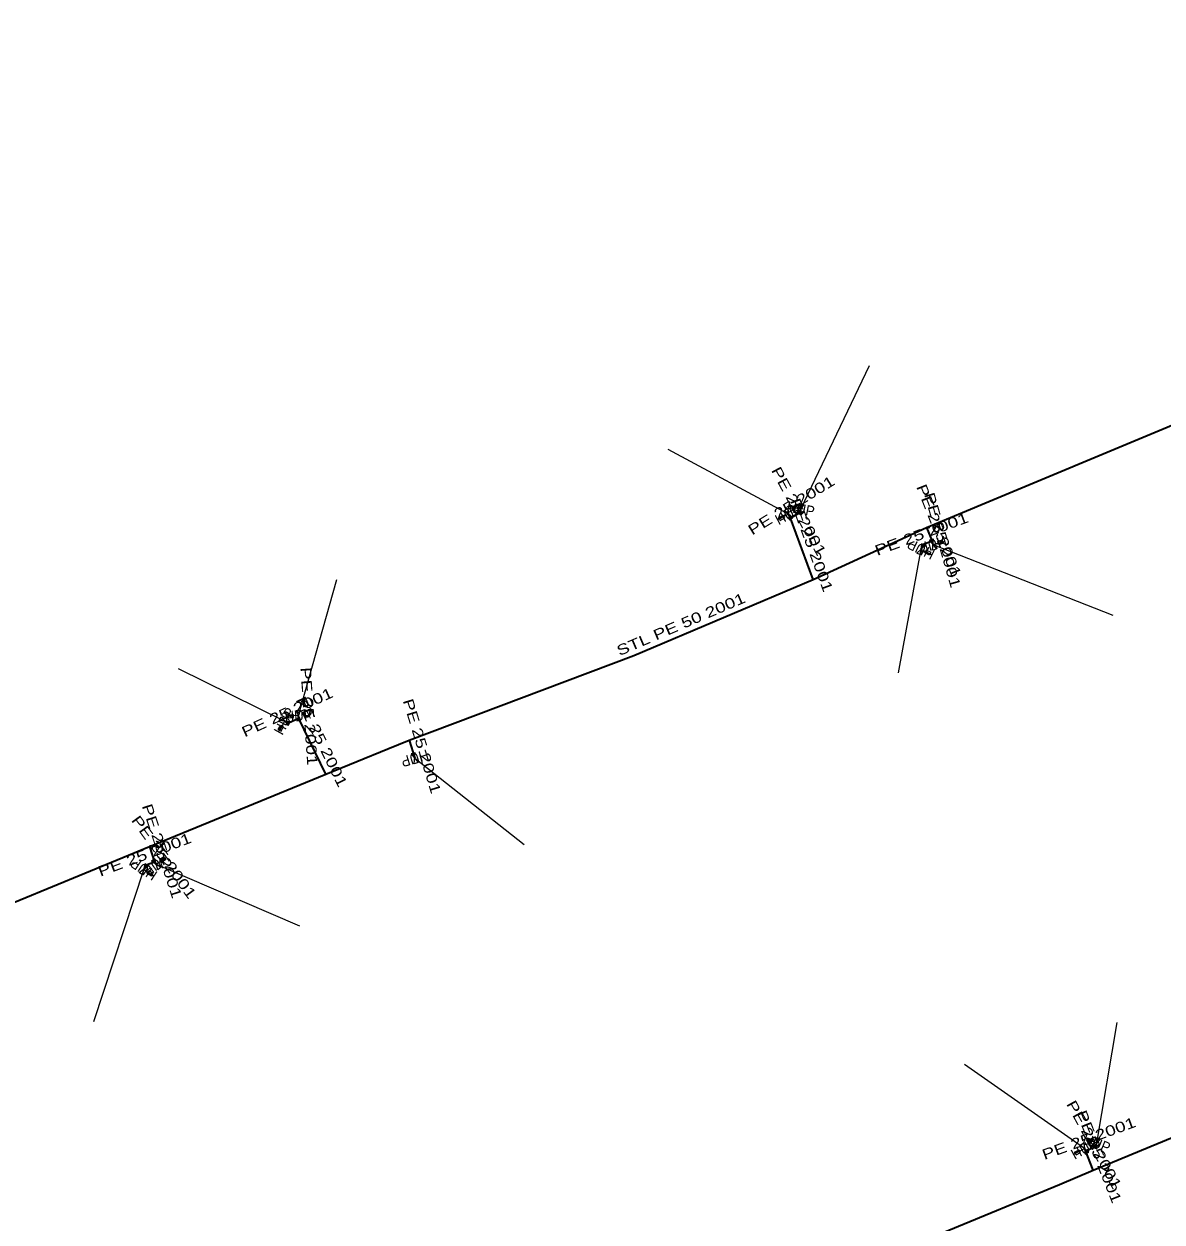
# Model space of a CAD drawing. Extents: x -737484 to -734496, y -1033882 to -1030666.
# Drawn here: x -735034.9 to -734925.7, y -1033417 to -1033302.1 of the extents above; entities that cross this region are included whole.
import ezdxf
from ezdxf.enums import TextEntityAlignment as Align

# ---------------------------------------------------------------- set-up
doc = ezdxf.new("R2010")
doc.units = 0
doc.header["$LTSCALE"] = 0.4
for name, color, linetype, lineweight in [('1', 7, 'Continuous', 13), ('22', 7, 'Continuous', 25), ('5', 7, 'Continuous', 35), ('7', 7, 'Continuous', 35)]:
    doc.layers.add(name, color=color, linetype=linetype, lineweight=lineweight)
doc.layers.add('2', color=7, linetype='Continuous')

msp = doc.modelspace()

# ---------------------------------------------------------------- linework, layer by layer
at = {"layer": '1'}
for p, q in [((-734962.092, -1033349.333), (-734962.401, -1033349.498)), ((-734961.55, -1033349.13), (-734961.991, -1033349.364)), ((-734960.93, -1033348.456), (-734961.273, -1033348.389)), ((-734960.38, -1033348.64), (-734960.87, -1033348.544)), ((-734948.85, -1033352.5), (-734948.4, -1033352.719)), ((-734948.366, -1033352.819), (-734948.051, -1033352.972)), ((-734947.7, -1033352.05), (-734947.219, -1033351.912)), ((-734947.126, -1033351.963), (-734946.79, -1033351.867)), ((-735009.89, -1033368.98), (-735010.124, -1033369.421)), ((-735009.128, -1033368.415), (-735009.477, -1033368.439)), ((-735008.55, -1033368.45), (-735009.048, -1033368.484)), ((-735010.226, -1033369.452), (-735010.39, -1033369.761)), ((-735022.19, -1033382.71), (-735021.785, -1033382.416)), ((-735021.68, -1033382.432), (-735021.397, -1033382.226)), ((-735023.4, -1033383.18), (-735022.98, -1033383.452)), ((-735022.958, -1033383.556), (-735022.665, -1033383.746)), ((-734932.499, -1033409.173), (-734932.826, -1033409.048)), ((-734933.709, -1033410.183), (-734934.015, -1033410.352)), ((-734933.17, -1033409.97), (-734933.607, -1033410.212)), ((-734931.99, -1033409.45), (-734932.456, -1033409.27))]:
    msp.add_line(p, q, dxfattribs=at)
for points in [[(-734961.361, -1033348.449), (-734961.333, -1033348.301), (-734960.842, -1033348.397), (-734960.87, -1033348.544)], [(-734961.317, -1033348.42), (-734961.302, -1033348.346), (-734960.885, -1033348.427), (-734960.9, -1033348.501)], [(-734960.48, -1033348.11), (-734960.088, -1033348.186), (-734960.671, -1033349.091), (-734960.279, -1033349.167)], [(-734962.432, -1033349.599), (-734962.503, -1033349.467), (-734962.061, -1033349.232), (-734961.991, -1033349.364)], [(-734962.416, -1033349.548), (-734962.451, -1033349.482), (-734962.076, -1033349.283), (-734962.041, -1033349.349)], [(-734962.432, -1033349.599), (-734962.362, -1033349.731), (-734961.921, -1033349.497), (-734961.991, -1033349.364)], [(-734961.961, -1033348.781), (-734961.608, -1033348.593), (-734961.491, -1033349.664), (-734961.138, -1033349.476)], [(-734961.361, -1033348.449), (-734961.39, -1033348.596), (-734960.899, -1033348.691), (-734960.87, -1033348.544)], [(-734947.368, -1033352.474), (-734947.753, -1033352.584), (-734947.644, -1033351.513), (-734948.029, -1033351.623)], [(-734946.738, -1033351.774), (-734946.78, -1033351.63), (-734947.26, -1033351.767), (-734947.219, -1033351.912)], [(-734946.738, -1033351.774), (-734946.697, -1033351.918), (-734947.178, -1033352.056), (-734947.219, -1033351.912)], [(-734948.888, -1033353.036), (-734949.247, -1033352.86), (-734948.45, -1033352.137), (-734948.809, -1033351.961)], [(-734947.951, -1033352.938), (-734948.016, -1033353.073), (-734948.466, -1033352.854), (-734948.4, -1033352.719)], [(-734948.001, -1033352.954), (-734948.034, -1033353.022), (-734948.416, -1033352.836), (-734948.383, -1033352.768)], [(-734947.951, -1033352.938), (-734947.885, -1033352.803), (-734948.334, -1033352.584), (-734948.4, -1033352.719)], [(-734946.765, -1033351.82), (-734946.744, -1033351.892), (-734947.152, -1033352.009), (-734947.173, -1033351.937)], [(-735010.423, -1033368.911), (-735010.229, -1033368.561), (-735009.548, -1033369.396), (-735009.354, -1033369.046)], [(-735009.547, -1033368.519), (-735009.558, -1033368.37), (-735009.059, -1033368.335), (-735009.048, -1033368.484)], [(-735009.547, -1033368.519), (-735009.537, -1033368.669), (-735009.038, -1033368.634), (-735009.048, -1033368.484)], [(-735009.512, -1033368.48), (-735009.517, -1033368.405), (-735009.093, -1033368.375), (-735009.088, -1033368.45)], [(-735008.784, -1033367.964), (-735008.385, -1033367.936), (-735008.714, -1033368.961), (-735008.315, -1033368.933)], [(-735010.359, -1033369.862), (-735010.491, -1033369.792), (-735010.257, -1033369.351), (-735010.124, -1033369.421)], [(-735010.374, -1033369.812), (-735010.44, -1033369.776), (-735010.24, -1033369.401), (-735010.174, -1033369.436)], [(-735010.359, -1033369.862), (-735010.227, -1033369.933), (-735009.992, -1033369.491), (-735010.124, -1033369.421)], [(-734997.062, -1033372.959), (-734997.445, -1033373.076), (-734997.354, -1033372.003), (-734997.737, -1033372.12)], [(-735023.503, -1033383.707), (-735023.839, -1033383.489), (-735022.958, -1033382.868), (-735023.294, -1033382.65)], [(-735021.734, -1033382.996), (-735022.057, -1033383.232), (-735022.322, -1033382.187), (-735022.645, -1033382.423)], [(-735021.38, -1033382.122), (-735021.469, -1033382), (-735021.873, -1033382.294), (-735021.785, -1033382.416)], [(-735021.38, -1033382.122), (-735021.292, -1033382.243), (-735021.697, -1033382.537), (-735021.785, -1033382.416)], [(-735021.389, -1033382.174), (-735021.345, -1033382.235), (-735021.689, -1033382.484), (-735021.733, -1033382.424)], [(-735022.561, -1033383.724), (-735022.643, -1033383.85), (-735023.062, -1033383.578), (-735022.98, -1033383.452)], [(-735022.613, -1033383.734), (-735022.654, -1033383.797), (-735023.01, -1033383.566), (-735022.969, -1033383.503)], [(-735022.561, -1033383.724), (-735022.479, -1033383.598), (-735022.898, -1033383.326), (-735022.98, -1033383.452)], [(-734932.923, -1033409.091), (-734932.977, -1033409.231), (-734932.51, -1033409.41), (-734932.456, -1033409.27)], [(-734932.923, -1033409.091), (-734932.869, -1033408.951), (-734932.403, -1033409.13), (-734932.456, -1033409.27)], [(-734932.874, -1033409.07), (-734932.847, -1033409), (-734932.451, -1033409.152), (-734932.478, -1033409.223)], [(-734931.988, -1033408.911), (-734931.617, -1033409.061), (-734932.362, -1033409.838), (-734931.991, -1033409.988)], [(-734934.044, -1033410.454), (-734934.117, -1033410.323), (-734933.68, -1033410.081), (-734933.607, -1033410.212)], [(-734934.029, -1033410.404), (-734934.065, -1033410.338), (-734933.693, -1033410.132), (-734933.657, -1033410.197)], [(-734934.044, -1033410.454), (-734933.971, -1033410.586), (-734933.534, -1033410.343), (-734933.607, -1033410.212)], [(-734933.587, -1033409.628), (-734933.237, -1033409.434), (-734933.102, -1033410.503), (-734932.752, -1033410.309)]]:
    msp.add_lwpolyline(points, close=True, dxfattribs=at)
at = {"layer": '22'}
for p, q in [((-734960.38, -1033348.639), (-734953.783, -1033334.862)), ((-734961.55, -1033349.129), (-734973.094, -1033342.925)), ((-734948.849, -1033352.499), (-734951.024, -1033364.358)), ((-734947.699, -1033352.049), (-734930.436, -1033358.824)), ((-735008.55, -1033368.449), (-735004.863, -1033355.403)), ((-735009.889, -1033368.979), (-735020.073, -1033363.972)), ((-734997.4, -1033372.54), (-734986.918, -1033380.822)), ((-735022.19, -1033382.71), (-735008.452, -1033388.624)), ((-735023.399, -1033383.179), (-735028.214, -1033397.82)), ((-734931.99, -1033409.45), (-734930.015, -1033397.887)), ((-734933.17, -1033409.969), (-734944.658, -1033401.919))]:
    msp.add_line(p, q, dxfattribs=at)
at = {"layer": '5'}
for points in [[(-735053.88, -1033393.79), (-735022.84, -1033381), (-735005.93, -1033374.05), (-735000, -1033371.64), (-734997.93, -1033370.8), (-734976.39, -1033362.7), (-734959.2, -1033355.38), (-734948.31, -1033350.41), (-734910.99, -1033334.84), (-734896.49, -1033328.75), (-734864.89, -1033315.68), (-734844.17, -1033307.16), (-734831.48, -1033302.12), (-734827.29, -1033302.17), (-734824.78, -1033302.66), (-734821.95, -1033304.62), (-734815.17, -1033312.18), (-734809.03, -1033319.75), (-734803.21, -1033327.69), (-734802.82, -1033328.28)], [(-735042.22, -1033456.86), (-735027.92, -1033450.86), (-735021.89, -1033448.42), (-735004.89, -1033441.65), (-735000, -1033439.618), (-734988.79, -1033434.96), (-734973.06, -1033428.66), (-734957.88, -1033422.63), (-734935.56, -1033413.41), (-734932.32, -1033412.04), (-734914.01, -1033404.47), (-734896.05, -1033397.2), (-734889.79, -1033394.87), (-734876.41, -1033389.06), (-734849.15, -1033377.86), (-734829.82, -1033369.94), (-734809.23, -1033361.56), (-734800.47, -1033357.83), (-734800.3, -1033357.79)]]:
    msp.add_lwpolyline(points, dxfattribs=at)
at = {"layer": '7'}
for p, q in [((-734961.35, -1033349.5), (-734961.55, -1033349.129)), ((-734959.2, -1033355.38), (-734961.35, -1033349.5)), ((-734948.31, -1033350.41), (-734947.79, -1033351.73)), ((-734947.79, -1033351.73), (-734947.699, -1033352.049)), ((-735008.53, -1033368.73), (-735008.55, -1033368.449)), ((-735005.93, -1033374.05), (-735008.53, -1033368.73)), ((-734997.93, -1033370.8), (-734997.4, -1033372.54)), ((-735022.84, -1033381), (-735022.35, -1033382.49)), ((-735022.35, -1033382.49), (-735022.19, -1033382.71)), ((-734933.06, -1033410.17), (-734933.17, -1033409.969)), ((-734932.32, -1033412.04), (-734933.06, -1033410.17))]:
    msp.add_line(p, q, dxfattribs=at)
for points in [[(-734961.35, -1033349.5), (-734960.44, -1033348.94), (-734960.38, -1033348.639)], [(-734947.79, -1033351.73), (-734948.63, -1033352.04), (-734948.849, -1033352.499)], [(-735008.53, -1033368.73), (-735009.52, -1033369.18), (-735009.889, -1033368.979)], [(-735022.35, -1033382.49), (-735023.15, -1033382.79), (-735023.399, -1033383.179)], [(-734933.06, -1033410.17), (-734932.15, -1033409.84), (-734931.99, -1033409.45)]]:
    msp.add_lwpolyline(points, dxfattribs=at)

# ---------------------------------------------------------------- texts
at = {"layer": '2', "width": 0.95}
for rotation, p in [(28, (-734961.3142, -1033349.57)), (349, (-734960.4749, -1033349.1291)), (154, (-734948.6293, -1033352.0495)), (196, (-734947.8367, -1033351.5678)), (61, (-735009.4509, -1033369.2209)), (4, (-735008.5144, -1033368.9474)), (197, (-734997.5453, -1033372.0608)), (216, (-735022.4836, -1033382.305)), (147, (-735023.1262, -1033382.7591)), (29, (-734932.9269, -1033410.4059)), (338, (-734932.1768, -1033409.913))]:
    msp.add_text('HUP', height=1, rotation=rotation, dxfattribs=at).set_placement(p, align=Align.CENTER)
at = {"layer": '5', "width": 1.35}
msp.add_text('STL PE 50 2001', height=1, rotation=23.066, dxfattribs=at).set_placement((-734971.6784, -1033360.1499), align=Align.CENTER)
at = {"layer": '7', "width": 1.35}
for rotation, p in [(298.328, (-734961.0091, -1033349.0762)), (31.608, (-734961.025, -1033348.713)), (291.501, (-734947.5845, -1033350.8857)), (285.922, (-734947.2632, -1033351.7523)), (290.085, (-734959.8054, -1033352.2673)), (20.256, (-734948.6216, -1033351.5032)), (274.071, (-735008.0412, -1033368.5535)), (24.444, (-735009.4224, -1033368.5864)), (296.046, (-735006.7803, -1033371.17)), (286.941, (-734997.1859, -1033371.5233)), (288.204, (-735022.1196, -1033381.5883)), (306.027, (-735021.8649, -1033382.3054)), (20.556, (-735023.1411, -1033382.252)), (298.69, (-734932.676, -1033409.829)), (291.59, (-734932.2246, -1033410.9205)), (19.933, (-734932.5775, -1033409.4622))]:
    msp.add_text('PE 25 2001', height=1, rotation=rotation, dxfattribs=at).set_placement(p, align=Align.CENTER)

doc.saveas('drawing.dxf')
